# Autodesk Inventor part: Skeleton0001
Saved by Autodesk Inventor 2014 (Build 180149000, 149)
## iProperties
Created: 2007-02
Part Number: Skeleton0001
Document SubType Name: Modeling
Designer: hendert
Density: 1 g/cm^3
Material: Generic
Appearance: Default
_SkeletonDoc: Frame Skeleton File
_Version: 15.0.0
Author: hendert
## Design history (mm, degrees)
sketch "Reference Skeleton"
